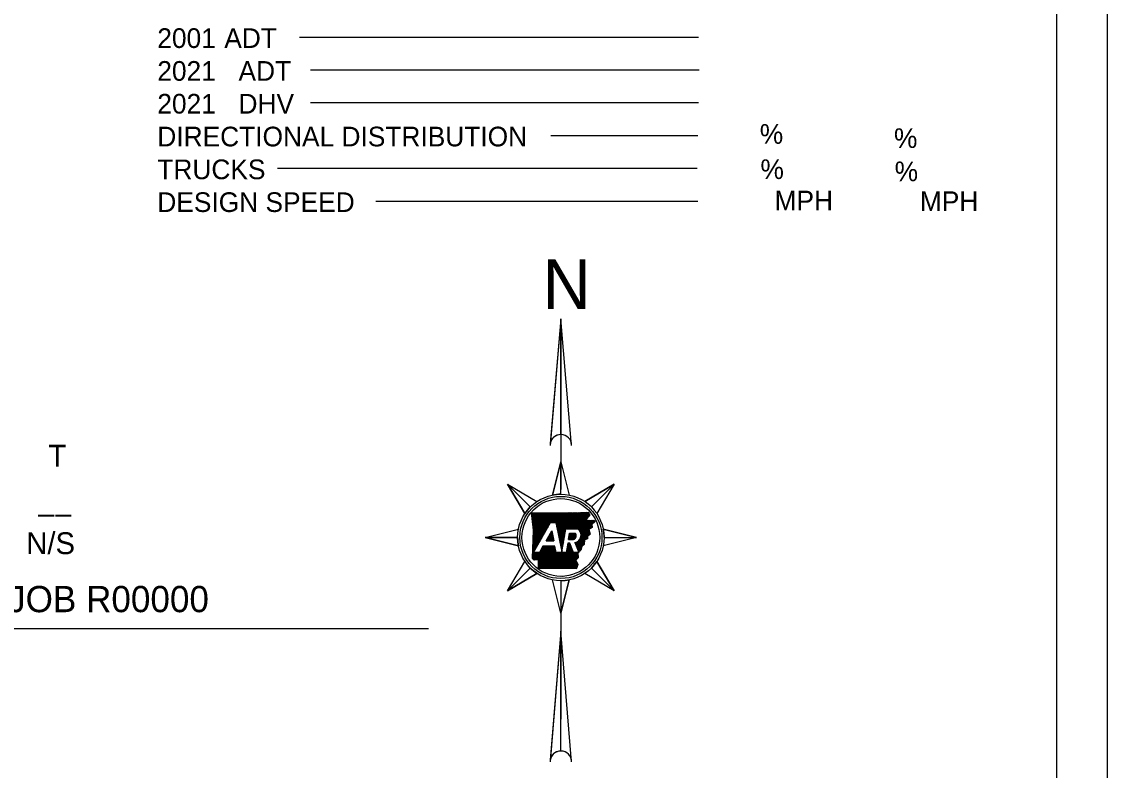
# Model space of a CAD drawing. Extents: x 23481 to 28196, y 1325020 to 1327623.
# Drawn here: x 26099 to 27092, y 1325809 to 1326493 of the extents above; entities that cross this region are included whole.
import ezdxf

# ---------------------------------------------------------------- set-up
doc = ezdxf.new("R2010")
doc.units = 0
doc.layers.add('S_ELECTRIC_UTILITIES_ANNOT', color=7, linetype='Continuous')
doc.layers.add('S_PRIMARY_CTL_ANNOT', color=7, linetype='Continuous')

msp = doc.modelspace()

# ---------------------------------------------------------------- linework, layer by layer
at = {"layer": 'S_ELECTRIC_UTILITIES_ANNOT'}
for p, q in [((27045.67, 1325448.4), (27045.67, 1327502.83)), ((26352.61, 1326479.36), (26717.87, 1326479.36)), ((26362.61, 1326449.36), (26718.49, 1326449.36)), ((26362.61, 1326419.36), (26717.87, 1326419.36)), ((26582.61, 1326389.36), (26717.25, 1326389.36)), ((26332.61, 1326359.36), (26716.63, 1326359.36)), ((26422.61, 1326329.36), (26717.25, 1326329.36)), ((26591.81, 1326221.54), (26582.07, 1326107.61)), ((26591.81, 1326221.54), (26591.81, 1326065.52)), ((26591.81, 1326115.82), (26591.81, 1326221.54)), ((26582.21, 1326109.2), (26582.65, 1326109.65)), ((26582.26, 1326109.82), (26583.16, 1326110.72)), ((26591.81, 1326090.84), (26584.11, 1326060.44)), ((26591.81, 1326061.2), (26591.81, 1326090.84)), ((26542.9, 1326070.58), (26563.86, 1326049.63)), ((26563.86, 1326049.63), (26542.9, 1326070.58)), ((26542.9, 1326070.58), (26558.96, 1326043.65)), ((26640.71, 1326070.58), (26613.78, 1326054.53)), ((26619.75, 1326049.63), (26640.71, 1326070.58)), ((26619.75, 1326049.63), (26640.71, 1326070.58)), ((26564.87, 1326043.95), (26565.22, 1326044.3)), ((26564.99, 1326042.96), (26566.34, 1326044.3)), ((26565.12, 1326041.97), (26567.45, 1326044.3)), ((26565.24, 1326040.97), (26568.57, 1326044.3)), ((26565.37, 1326039.98), (26569.69, 1326044.3)), ((26565.49, 1326038.98), (26570.8, 1326044.3)), ((26565.61, 1326037.99), (26571.92, 1326044.3)), ((26565.74, 1326037), (26573.04, 1326044.3)), ((26565.86, 1326036), (26574.16, 1326044.3)), ((26565.98, 1326035.01), (26575.27, 1326044.3)), ((26566.11, 1326034.01), (26576.39, 1326044.3)), ((26566.23, 1326033.02), (26577.51, 1326044.3)), ((26566.36, 1326032.03), (26578.62, 1326044.3)), ((26566.48, 1326031.03), (26579.74, 1326044.29)), ((26566.52, 1326019.89), (26590.94, 1326044.32)), ((26566.56, 1326021.05), (26589.82, 1326044.31)), ((26566.59, 1326022.2), (26588.7, 1326044.31)), ((26566.6, 1326030.04), (26580.86, 1326044.3)), ((26566.63, 1326023.36), (26587.58, 1326044.31)), ((26566.67, 1326024.52), (26586.46, 1326044.31)), ((26566.71, 1326025.67), (26585.34, 1326044.3)), ((26566.73, 1326029.04), (26581.98, 1326044.3)), ((26566.75, 1326026.83), (26584.22, 1326044.3)), ((26566.79, 1326027.98), (26583.1, 1326044.3)), ((26583.12, 1326035.37), (26592.06, 1326044.32)), ((26584.23, 1326035.37), (26593.18, 1326044.32)), ((26585.35, 1326035.37), (26594.31, 1326044.33)), ((26586.47, 1326035.37), (26595.45, 1326044.35)), ((26587.17, 1326034.95), (26596.58, 1326044.37)), ((26587.36, 1326034.03), (26597.72, 1326044.38)), ((26587.56, 1326033.11), (26598.85, 1326044.4)), ((26587.76, 1326032.19), (26599.99, 1326044.42)), ((26587.95, 1326031.27), (26601.12, 1326044.44)), ((26588.15, 1326030.35), (26602.26, 1326044.45)), ((26588.35, 1326029.43), (26603.39, 1326044.47)), ((26588.55, 1326028.51), (26604.53, 1326044.49)), ((26588.74, 1326027.59), (26605.66, 1326044.51)), ((26588.94, 1326026.67), (26606.8, 1326044.52)), ((26589.14, 1326025.74), (26607.94, 1326044.54)), ((26589.33, 1326024.82), (26609.07, 1326044.56)), ((26589.53, 1326023.9), (26610.21, 1326044.58)), ((26589.73, 1326022.98), (26611.35, 1326044.61)), ((26597.49, 1326029.63), (26612.5, 1326044.63)), ((26598.61, 1326029.63), (26613.64, 1326044.66)), ((26599.73, 1326029.63), (26614.79, 1326044.69)), ((26600.85, 1326029.63), (26615.93, 1326044.71)), ((26601.96, 1326029.63), (26617.08, 1326044.74)), ((26603.08, 1326029.63), (26617.33, 1326043.87)), ((26604.2, 1326029.63), (26617.87, 1326043.29)), ((26605.32, 1326029.63), (26618.01, 1326042.32)), ((26606.44, 1326029.63), (26615.46, 1326038.65)), ((26566.4, 1326016.42), (26578.64, 1326028.66)), ((26566.44, 1326017.58), (26580.1, 1326031.24)), ((26566.48, 1326018.74), (26581.56, 1326033.82)), ((26566.85, 1326007.84), (26582.44, 1326035.37)), ((26582.44, 1326035.37), (26587.08, 1326035.37)), ((26596.48, 1326029.63), (26607.31, 1326029.63)), ((26607.45, 1326029.53), (26615.24, 1326037.31)), ((26608.06, 1326029.02), (26616.42, 1326037.37)), ((26608.61, 1326028.45), (26617.59, 1326037.43)), ((26609.06, 1326019.95), (26617.6, 1326028.49)), ((26609.09, 1326027.81), (26618.77, 1326037.49)), ((26609.5, 1326027.11), (26619.95, 1326037.56)), ((26609.85, 1326026.33), (26621.13, 1326037.62)), ((26610.03, 1326022.04), (26620.17, 1326032.19)), ((26610.1, 1326025.47), (26622.19, 1326037.56)), ((26610.25, 1326024.51), (26622.71, 1326036.96)), ((26610.26, 1326023.39), (26620.05, 1326033.18)), ((26618.92, 1326029.82), (26620.3, 1326031.2)), ((26622.22, 1326035.35), (26623.23, 1326036.37)), ((26660.97, 1326021.68), (26630.57, 1326029.38)), ((26522.65, 1326021.68), (26552.29, 1326021.68)), ((26552.29, 1326021.68), (26522.65, 1326021.68)), ((26522.65, 1326021.68), (26553.05, 1326013.98)), ((26566.29, 1326012.95), (26574.27, 1326020.93)), ((26566.33, 1326014.11), (26575.73, 1326023.51)), ((26566.36, 1326015.27), (26577.18, 1326026.09)), ((26578.32, 1326018.64), (26583.42, 1326027.65)), ((26578.32, 1326018.64), (26585.35, 1326018.64)), ((26578.37, 1326018.64), (26584.12, 1326024.39)), ((26579.49, 1326018.64), (26584.32, 1326023.47)), ((26579.71, 1326021.1), (26583.92, 1326025.31)), ((26580.61, 1326018.64), (26584.51, 1326022.55)), ((26581.17, 1326023.67), (26583.72, 1326026.23)), ((26581.73, 1326018.64), (26584.71, 1326021.63)), ((26582.63, 1326026.25), (26583.53, 1326027.15)), ((26582.85, 1326018.64), (26584.91, 1326020.71)), ((26583.96, 1326018.64), (26585.1, 1326019.79)), ((26585.08, 1326018.64), (26585.3, 1326018.86)), ((26589.93, 1326022.06), (26596.27, 1326028.4)), ((26590.12, 1326021.14), (26596.03, 1326027.05)), ((26590.32, 1326020.22), (26595.8, 1326025.7)), ((26590.52, 1326019.3), (26595.56, 1326024.34)), ((26590.71, 1326018.38), (26595.32, 1326022.99)), ((26590.91, 1326017.46), (26595.09, 1326021.64)), ((26591.11, 1326016.54), (26594.85, 1326020.28)), ((26591.3, 1326015.62), (26594.62, 1326018.93)), ((26598.83, 1326019.86), (26603.48, 1326019.86)), ((26598.84, 1326019.86), (26604.72, 1326025.74)), ((26599.07, 1326021.21), (26603.6, 1326025.74)), ((26599.3, 1326022.56), (26602.48, 1326025.74)), ((26599.54, 1326023.92), (26601.37, 1326025.74)), ((26599.77, 1326025.27), (26600.25, 1326025.74)), ((26599.86, 1326025.74), (26604.94, 1326025.74)), ((26599.96, 1326019.86), (26605.34, 1326025.25)), ((26601.07, 1326019.86), (26605.72, 1326024.51)), ((26602.19, 1326019.86), (26605.93, 1326023.6)), ((26603.31, 1326019.86), (26605.83, 1326022.38)), ((26605.41, 1326015.19), (26617.81, 1326027.58)), ((26605.71, 1326014.38), (26618.01, 1326026.68)), ((26606.02, 1326013.56), (26618.22, 1326025.77)), ((26606.32, 1326012.74), (26618.43, 1326024.86)), ((26606.62, 1326011.93), (26613.32, 1326018.63)), ((26614.61, 1326019.92), (26616.18, 1326021.49)), ((26631.33, 1326021.68), (26660.97, 1326021.68)), ((26631.33, 1326021.68), (26660.97, 1326021.68)), ((26566.13, 1326008.33), (26568.43, 1326010.63)), ((26566.17, 1326009.49), (26569.89, 1326013.2)), ((26566.21, 1326010.64), (26571.35, 1326015.78)), ((26566.25, 1326011.8), (26572.81, 1326018.36)), ((26566.38, 1326001.87), (26578.12, 1326013.61)), ((26567.04, 1326001.41), (26579.24, 1326013.61)), ((26567.84, 1326001.1), (26580.36, 1326013.61)), ((26569.17, 1326001.31), (26581.48, 1326013.61)), ((26570.31, 1326001.32), (26582.6, 1326013.61)), ((26571.18, 1326001.08), (26583.71, 1326013.61)), ((26571.22, 1325998.89), (26585.95, 1326013.61)), ((26571.22, 1326000), (26584.83, 1326013.61)), ((26571.23, 1325997.77), (26586.54, 1326013.08)), ((26571.23, 1325996.66), (26586.73, 1326012.16)), ((26571.23, 1325995.54), (26586.93, 1326011.24)), ((26571.23, 1325994.43), (26587.13, 1326010.32)), ((26571.25, 1325993.33), (26587.33, 1326009.4)), ((26575.47, 1326013.61), (26572.2, 1326007.84)), ((26573.47, 1326010.07), (26577.01, 1326013.61)), ((26574.93, 1326012.65), (26575.89, 1326013.61)), ((26586.42, 1326013.61), (26575.47, 1326013.61)), ((26582.41, 1325993.31), (26601.64, 1326012.54)), ((26583.53, 1325993.31), (26601.94, 1326011.72)), ((26584.64, 1325993.31), (26602.24, 1326010.9)), ((26585.76, 1325993.3), (26602.54, 1326010.09)), ((26586.88, 1325993.3), (26602.84, 1326009.27)), ((26591.5, 1326014.7), (26594.38, 1326017.57)), ((26591.7, 1326013.77), (26594.14, 1326016.22)), ((26591.9, 1326012.85), (26593.91, 1326014.87)), ((26592.09, 1326011.93), (26593.67, 1326013.51)), ((26592.29, 1326011.01), (26593.44, 1326012.16)), ((26592.49, 1326010.09), (26593.2, 1326010.81)), ((26592.68, 1326009.17), (26592.97, 1326009.45)), ((26596.93, 1326008.94), (26601.34, 1326013.35)), ((26597.17, 1326010.3), (26601.04, 1326014.17)), ((26597.4, 1326011.65), (26600.73, 1326014.98)), ((26597.64, 1326013.01), (26600.43, 1326015.8)), ((26597.87, 1326014.36), (26600.11, 1326016.59)), ((26598.11, 1326015.71), (26598.99, 1326016.59)), ((26600.14, 1326016.59), (26598.26, 1326016.59)), ((26603.37, 1326007.84), (26600.14, 1326016.59)), ((26604.72, 1326017.06), (26608.13, 1326007.84)), ((26604.81, 1326016.83), (26605.15, 1326017.16)), ((26605.11, 1326016.01), (26607.24, 1326018.14)), ((26606.92, 1326011.11), (26613.2, 1326017.39)), ((26607.22, 1326010.3), (26613.07, 1326016.15)), ((26607.52, 1326009.48), (26610.95, 1326012.91)), ((26607.83, 1326008.66), (26610.47, 1326011.31)), ((26565.96, 1326002.57), (26571.23, 1326007.84)), ((26565.98, 1326003.71), (26570.11, 1326007.84)), ((26566.02, 1326004.86), (26568.99, 1326007.84)), ((26566.06, 1326006.02), (26567.88, 1326007.84)), ((26566.1, 1326007.17), (26566.97, 1326008.05)), ((26572.2, 1326007.84), (26566.85, 1326007.84)), ((26572.37, 1325993.33), (26587.52, 1326008.48)), ((26573.48, 1325993.32), (26588, 1326007.84)), ((26574.6, 1325993.32), (26589.11, 1326007.84)), ((26575.72, 1325993.32), (26590.23, 1326007.84)), ((26576.83, 1325993.32), (26591.35, 1326007.84)), ((26577.95, 1325993.32), (26592.47, 1326007.84)), ((26579.06, 1325993.32), (26593.58, 1326007.84)), ((26580.18, 1325993.31), (26594.7, 1326007.84)), ((26581.3, 1325993.31), (26595.82, 1326007.84)), ((26596.74, 1326007.84), (26587.66, 1326007.84)), ((26587.99, 1325993.3), (26603.15, 1326008.45)), ((26589.11, 1325993.3), (26603.65, 1326007.84)), ((26590.22, 1325993.3), (26604.76, 1326007.84)), ((26591.34, 1325993.3), (26605.88, 1326007.84)), ((26592.46, 1325993.29), (26607, 1326007.84)), ((26593.57, 1325993.29), (26607.37, 1326007.09)), ((26594.69, 1325993.29), (26607.42, 1326006.02)), ((26595.8, 1325993.29), (26607.47, 1326004.96)), ((26596.92, 1325993.29), (26607.52, 1326003.89)), ((26598.04, 1325993.28), (26605.69, 1326000.93)), ((26599.15, 1325993.28), (26606.03, 1326000.16)), ((26600.27, 1325993.28), (26606.38, 1325999.39)), ((26601.38, 1325993.28), (26606.72, 1325998.62)), ((26608.13, 1326007.84), (26603.37, 1326007.84)), ((26640.71, 1325972.78), (26624.66, 1325999.71)), ((26542.9, 1325972.78), (26563.86, 1325993.73)), ((26563.86, 1325993.73), (26542.9, 1325972.78)), ((26542.9, 1325972.78), (26569.84, 1325988.83)), ((26602.5, 1325993.28), (26607.07, 1325997.84)), ((26603.62, 1325993.28), (26607.36, 1325997.01)), ((26604.73, 1325993.27), (26606.85, 1325995.39)), ((26605.85, 1325993.27), (26606.34, 1325993.77)), ((26619.75, 1325993.73), (26640.71, 1325972.78)), ((26619.75, 1325993.73), (26640.71, 1325972.78)), ((26591.81, 1325952.52), (26599.51, 1325982.92)), ((26591.81, 1325982.16), (26591.81, 1325982.16)), ((26591.81, 1325982.16), (26591.81, 1325855.64)), ((26591.81, 1325982.16), (26591.81, 1325952.52)), ((25802.76, 1325938.35), (26470.69, 1325938.35)), ((26591.81, 1325936), (26582.06, 1325818.07)), ((26591.81, 1325826.33), (26591.81, 1325936))]:
    msp.add_line(p, q, dxfattribs=at)
for points in [[(26601.69, 1326105.94), (26591.81, 1326221.54), (26581.93, 1326105.94)], [(26584.11, 1326060.44), (26591.81, 1326090.84), (26599.51, 1326060.44)], [(26558.96, 1326043.65), (26542.9, 1326070.58), (26569.84, 1326054.53)], [(26613.78, 1326054.53), (26640.71, 1326070.58), (26624.66, 1326043.65)], [(26564.83, 1326044.3), (26580.25, 1326044.29), (26593.78, 1326044.32), (26609.75, 1326044.57), (26617.15, 1326044.74)], [(26565.94, 1326002.58), (26566.8, 1326028.45), (26564.83, 1326044.3)], [(26553.05, 1326013.98), (26522.65, 1326021.68), (26553.05, 1326029.38)], [(26587.08, 1326035.37), (26592.81, 1326008.57), (26596.48, 1326029.63)], [(26621.99, 1326037.66), (26623.33, 1326036.26), (26620, 1326033.53), (26620.36, 1326030.77), (26617.51, 1326028.89), (26618.48, 1326024.64), (26616.28, 1326022.63), (26616.09, 1326020.45), (26613.41, 1326019.49), (26613, 1326015.37), (26611.07, 1326013.31), (26610.14, 1326010.21), (26607.35, 1326007.65), (26607.56, 1326003.13), (26605.66, 1326001), (26607.39, 1325997.12), (26606.19, 1325993.27)], [(26614.86, 1326037.29), (26622.1, 1326037.67)], [(26630.57, 1326029.38), (26660.97, 1326021.68), (26630.57, 1326013.98)], [(26583.42, 1326027.65), (26585.35, 1326018.64)], [(26598.83, 1326019.86), (26599.86, 1326025.74)], [(26587.66, 1326007.84), (26586.42, 1326013.61)], [(26598.26, 1326016.59), (26596.74, 1326007.84)], [(26569.84, 1325988.83), (26542.9, 1325972.78), (26558.96, 1325999.71)], [(26606.19, 1325993.27), (26571.24, 1325993.33), (26571.22, 1326001.04)], [(26624.66, 1325999.71), (26640.71, 1325972.78), (26613.78, 1325988.83)], [(26599.51, 1325982.92), (26591.81, 1325952.52), (26584.11, 1325982.92)], [(26601.69, 1325816.45), (26591.81, 1325936), (26581.93, 1325816.45)]]:
    msp.add_lwpolyline(points, dxfattribs=at)
for radius in [39.52, 37.54, 35.57]:
    msp.add_circle((26591.81, 1326021.68), radius, dxfattribs=at)
for centre, radius, start, end in [((26591.81, 1326105.94), 9.88, 0, 180), ((26591.81, 1326105.94), 9.88, 90, 170.22959), ((26591.81, 1326021.68), 39.52, 90, 101.22909), ((26591.81, 1326021.68), 39.52, 135, 146.22909), ((26591.81, 1326021.68), 39.52, 45, 56.22909), ((26603.28, 1326023.91), 7, 281.86262, 54.87052), ((26591.81, 1326021.68), 39.52, 0, 11.22909), ((26591.81, 1326021.68), 39.52, 180, 191.22909), ((26602.36, 1326023.26), 3.58, 288.12683, 43.89016), ((26591.81, 1326021.68), 39.52, 315, 326.22909), ((26591.81, 1326021.68), 39.52, 225, 236.22909), ((26591.81, 1326021.68), 39.52, 270, 281.22909), ((26591.81, 1325816.45), 9.88, 0, 180), ((26591.81, 1325816.45), 9.88, 90, 170.5511)]:
    msp.add_arc(centre, radius, start, end, dxfattribs=at)
for points in [[(26617.15, 1326044.74), (26617.2, 1326044.32), (26617.33, 1326044.1), (26617.35, 1326043.7), (26617.51, 1326043.53), (26617.79, 1326043.36), (26618.03, 1326043.08), (26618.09, 1326042.76), (26618.02, 1326042.42), (26618, 1326042.05), (26617.96, 1326041.73), (26617.9, 1326041.43), (26617.67, 1326041.19), (26617.45, 1326041.02), (26617.25, 1326040.82), (26617.11, 1326040.61), (26616.86, 1326040.38), (26616.61, 1326040.15), (26616.41, 1326039.94), (26616.21, 1326039.67), (26616.12, 1326039.37), (26615.9, 1326039.16), (26615.73, 1326038.97), (26615.5, 1326038.71), (26615.38, 1326038.46), (26615.16, 1326038.16), (26615.12, 1326037.88), (26614.97, 1326037.65), (26614.96, 1326037.61)], [(26571.22, 1326001.04), (26571.26, 1326001.02), (26571.07, 1326001.15), (26570.83, 1326001.27), (26570.55, 1326001.29), (26570.2, 1326001.34), (26569.9, 1326001.37), (26569.6, 1326001.57), (26569.27, 1326001.36), (26568.91, 1326001.21), (26568.7, 1326001.38), (26568.42, 1326001.26), (26568.23, 1326001.32), (26567.9, 1326001.09), (26567.58, 1326001.18), (26567.35, 1326001.11), (26567.07, 1326001.12), (26567.01, 1326001.44), (26566.73, 1326001.49), (26566.5, 1326001.63), (26566.33, 1326001.96), (26566.22, 1326002.22), (26565.94, 1326002.58)]]:
    msp.add_spline(points, degree=3, dxfattribs=at)
at = {"layer": 'S_PRIMARY_CTL_ANNOT'}
msp.add_lwpolyline([(23808.34, 1327542.3), (27091.73, 1327542.3), (27091.73, 1325408.97), (23808.34, 1325408.97)], close=True, dxfattribs=at)

# ---------------------------------------------------------------- texts
at = {"layer": 'S_ELECTRIC_UTILITIES_ANNOT'}
for s, height, p in [('2001', 18, (26222.61, 1326469.36)), (' ADT', 18, (26277.21, 1326469.36)), ('2021', 18, (26222.61, 1326439.36)), (' ADT', 18, (26290.21, 1326439.36)), ('2021', 18, (26222.61, 1326409.36)), (' DHV', 18, (26290.21, 1326409.36)), ('DIRECTIONAL DISTRIBUTION', 18, (26222.61, 1326379.36)), ('  %', 18, (26760.44, 1326381.73)), ('   %', 18, (26876.52, 1326377.88)), ('TRUCKS', 18, (26222.61, 1326349.36)), ('  %', 18, (26761.08, 1326349.5)), ('   %', 18, (26877.16, 1326347.51)), ('DESIGN SPEED', 18, (26222.61, 1326319.36)), (' MPH', 18, (26780.62, 1326320.83)), (' MPH', 18, (26913.58, 1326320.21)), ('N', 45.6, (26575.15, 1326230.51)), ('T', 20, (26123.04, 1326086.45)), ('__', 20, (26114.01, 1326046.45)), ('N/S', 20, (26102.72, 1326006.45)), ('DWB 7-27-17', 0.7685, (26589.39, 1325985.45)), ('STA. __+__ - END  JOB R00000', 24, (25801.58, 1325953.37))]:
    msp.add_text(s, height=height, dxfattribs=at).set_placement(p)

doc.saveas('drawing.dxf')
